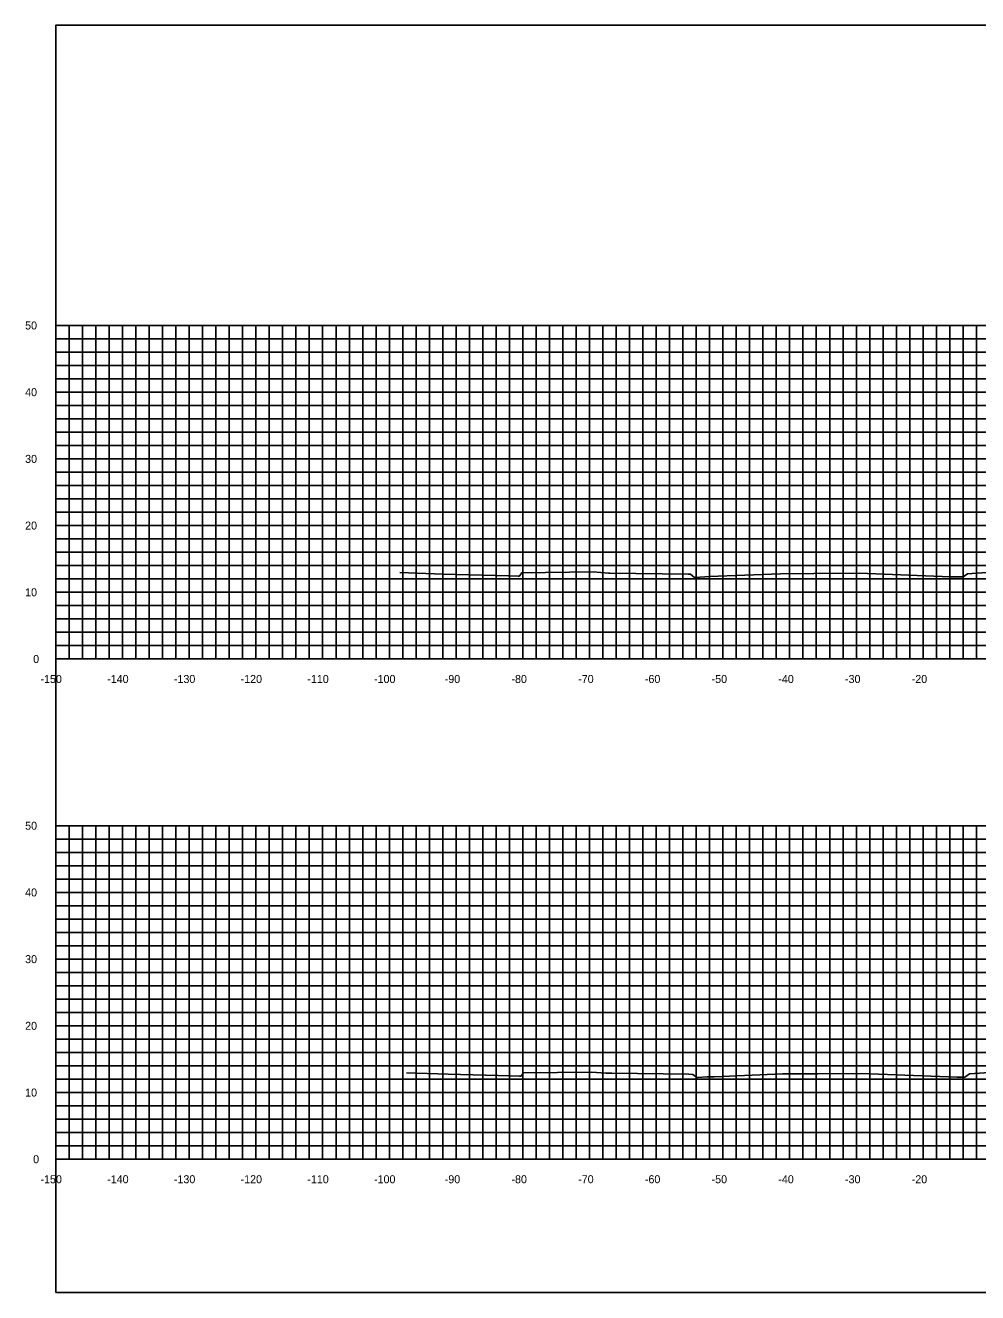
# Model space of a CAD drawing. Extents: x 1797714 to 1804825, y 249015 to 250269.
# Drawn here: x 1803809.6 to 1803952.3, y 249628.2 to 249818.2 of the extents above; entities that cross this region are included whole.
import ezdxf

# ---------------------------------------------------------------- set-up
doc = ezdxf.new("R2010")
doc.units = 0
for name, color, linetype in [('10', 7, 'Continuous'), ('31', 7, 'Continuous'), ('60', 7, 'Continuous'), ('Level 62', 7, 'Continuous'), ('M-ROADS', 7, 'Continuous')]:
    doc.layers.add(name, color=color, linetype=linetype)

msp = doc.modelspace()

# ---------------------------------------------------------------- linework, layer by layer
msp.add_lwpolyline([(1803814.16, 249628.17), (1804114.16, 249628.17), (1804114.16, 249818.17), (1803814.16, 249818.17)], close=True)
at = {"layer": '60'}
for p, q in [((1803814.1, 249773.17), (1803814.16, 249773.17)), ((1803814.16, 249723.17), (1803814.16, 249773.17)), ((1803814.1, 249763.17), (1803814.16, 249763.17)), ((1803814.1, 249753.17), (1803814.16, 249753.17)), ((1803814.1, 249743.17), (1803814.16, 249743.17)), ((1803814.1, 249733.17), (1803814.16, 249733.17)), ((1803814.1, 249723.17), (1803814.16, 249723.17)), ((1803814.16, 249723.17), (1804114.16, 249723.17)), ((1803814.16, 249723.11), (1803814.16, 249723.17)), ((1803824.16, 249723.11), (1803824.16, 249723.17)), ((1803834.16, 249723.11), (1803834.16, 249723.17)), ((1803844.16, 249723.11), (1803844.16, 249723.17)), ((1803854.16, 249723.11), (1803854.16, 249723.17)), ((1803864.16, 249723.11), (1803864.16, 249723.17)), ((1803874.16, 249723.11), (1803874.16, 249723.17)), ((1803884.16, 249723.11), (1803884.16, 249723.17)), ((1803894.16, 249723.11), (1803894.16, 249723.17)), ((1803904.16, 249723.11), (1803904.16, 249723.17)), ((1803914.16, 249723.11), (1803914.16, 249723.17)), ((1803924.16, 249723.11), (1803924.16, 249723.17)), ((1803934.16, 249723.11), (1803934.16, 249723.17)), ((1803944.16, 249723.11), (1803944.16, 249723.17)), ((1803814.1, 249698.17), (1803814.16, 249698.17)), ((1803814.16, 249648.17), (1803814.16, 249698.17)), ((1803814.1, 249688.17), (1803814.16, 249688.17)), ((1803814.1, 249678.17), (1803814.16, 249678.17)), ((1803814.1, 249668.17), (1803814.16, 249668.17)), ((1803814.1, 249658.17), (1803814.16, 249658.17)), ((1803814.1, 249648.17), (1803814.16, 249648.17)), ((1803814.16, 249648.17), (1804114.16, 249648.17)), ((1803814.16, 249648.11), (1803814.16, 249648.17)), ((1803824.16, 249648.11), (1803824.16, 249648.17)), ((1803834.16, 249648.11), (1803834.16, 249648.17)), ((1803844.16, 249648.11), (1803844.16, 249648.17)), ((1803854.16, 249648.11), (1803854.16, 249648.17)), ((1803864.16, 249648.11), (1803864.16, 249648.17)), ((1803874.16, 249648.11), (1803874.16, 249648.17)), ((1803884.16, 249648.11), (1803884.16, 249648.17)), ((1803894.16, 249648.11), (1803894.16, 249648.17)), ((1803904.16, 249648.11), (1803904.16, 249648.17)), ((1803914.16, 249648.11), (1803914.16, 249648.17)), ((1803924.16, 249648.11), (1803924.16, 249648.17)), ((1803934.16, 249648.11), (1803934.16, 249648.17)), ((1803944.16, 249648.11), (1803944.16, 249648.17))]:
    msp.add_line(p, q, dxfattribs=at)
at = {"layer": 'Level 62'}
for p, q in [((1803814.16, 249773.17), (1804114.16, 249773.17)), ((1803814.16, 249723.17), (1803814.16, 249773.17)), ((1803816.16, 249723.17), (1803816.16, 249773.17)), ((1803818.16, 249723.17), (1803818.16, 249773.17)), ((1803820.16, 249723.17), (1803820.16, 249773.17)), ((1803822.16, 249723.17), (1803822.16, 249773.17)), ((1803824.16, 249723.17), (1803824.16, 249773.17)), ((1803826.16, 249723.17), (1803826.16, 249773.17)), ((1803828.16, 249723.17), (1803828.16, 249773.17)), ((1803830.16, 249723.17), (1803830.16, 249773.17)), ((1803832.16, 249723.17), (1803832.16, 249773.17)), ((1803834.16, 249723.17), (1803834.16, 249773.17)), ((1803836.16, 249723.17), (1803836.16, 249773.17)), ((1803838.16, 249723.17), (1803838.16, 249773.17)), ((1803840.16, 249723.17), (1803840.16, 249773.17)), ((1803842.16, 249723.17), (1803842.16, 249773.17)), ((1803844.16, 249723.17), (1803844.16, 249773.17)), ((1803846.16, 249723.17), (1803846.16, 249773.17)), ((1803848.16, 249723.17), (1803848.16, 249773.17)), ((1803850.16, 249723.17), (1803850.16, 249773.17)), ((1803852.16, 249723.17), (1803852.16, 249773.17)), ((1803854.16, 249723.17), (1803854.16, 249773.17)), ((1803856.16, 249723.17), (1803856.16, 249773.17)), ((1803858.16, 249723.17), (1803858.16, 249773.17)), ((1803860.16, 249723.17), (1803860.16, 249773.17)), ((1803862.16, 249723.17), (1803862.16, 249773.17)), ((1803864.16, 249723.17), (1803864.16, 249773.17)), ((1803866.16, 249723.17), (1803866.16, 249773.17)), ((1803868.16, 249723.17), (1803868.16, 249773.17)), ((1803870.16, 249723.17), (1803870.16, 249773.17)), ((1803872.16, 249723.17), (1803872.16, 249773.17)), ((1803874.16, 249723.17), (1803874.16, 249773.17)), ((1803876.16, 249723.17), (1803876.16, 249773.17)), ((1803878.16, 249723.17), (1803878.16, 249773.17)), ((1803880.16, 249723.17), (1803880.16, 249773.17)), ((1803882.16, 249723.17), (1803882.16, 249773.17)), ((1803884.16, 249723.17), (1803884.16, 249773.17)), ((1803886.16, 249723.17), (1803886.16, 249773.17)), ((1803888.16, 249723.17), (1803888.16, 249773.17)), ((1803890.16, 249723.17), (1803890.16, 249773.17)), ((1803892.16, 249723.17), (1803892.16, 249773.17)), ((1803894.16, 249723.17), (1803894.16, 249773.17)), ((1803896.16, 249723.17), (1803896.16, 249773.17)), ((1803898.16, 249723.17), (1803898.16, 249773.17)), ((1803900.16, 249723.17), (1803900.16, 249773.17)), ((1803902.16, 249723.17), (1803902.16, 249773.17)), ((1803904.16, 249723.17), (1803904.16, 249773.17)), ((1803906.16, 249723.17), (1803906.16, 249773.17)), ((1803908.16, 249723.17), (1803908.16, 249773.17)), ((1803910.16, 249723.17), (1803910.16, 249773.17)), ((1803912.16, 249723.17), (1803912.16, 249773.17)), ((1803914.16, 249723.17), (1803914.16, 249773.17)), ((1803916.16, 249723.17), (1803916.16, 249773.17)), ((1803918.16, 249723.17), (1803918.16, 249773.17)), ((1803920.16, 249723.17), (1803920.16, 249773.17)), ((1803922.16, 249723.17), (1803922.16, 249773.17)), ((1803924.16, 249723.17), (1803924.16, 249773.17)), ((1803926.16, 249723.17), (1803926.16, 249773.17)), ((1803928.16, 249723.17), (1803928.16, 249773.17)), ((1803930.16, 249723.17), (1803930.16, 249773.17)), ((1803932.16, 249723.17), (1803932.16, 249773.17)), ((1803934.16, 249723.17), (1803934.16, 249773.17)), ((1803936.16, 249723.17), (1803936.16, 249773.17)), ((1803938.16, 249723.17), (1803938.16, 249773.17)), ((1803940.16, 249723.17), (1803940.16, 249773.17)), ((1803942.16, 249723.17), (1803942.16, 249773.17)), ((1803944.16, 249723.17), (1803944.16, 249773.17)), ((1803946.16, 249723.17), (1803946.16, 249773.17)), ((1803948.16, 249723.17), (1803948.16, 249773.17)), ((1803950.16, 249723.17), (1803950.16, 249773.17)), ((1803952.16, 249723.17), (1803952.16, 249773.17)), ((1803814.16, 249771.17), (1804114.16, 249771.17)), ((1803814.16, 249769.17), (1804114.16, 249769.17)), ((1803814.16, 249767.17), (1804114.16, 249767.17)), ((1803814.16, 249765.17), (1804114.16, 249765.17)), ((1803814.16, 249763.17), (1804114.16, 249763.17)), ((1803814.16, 249761.17), (1804114.16, 249761.17)), ((1803814.16, 249759.17), (1804114.16, 249759.17)), ((1803814.16, 249757.17), (1804114.16, 249757.17)), ((1803814.16, 249755.17), (1804114.16, 249755.17)), ((1803814.16, 249753.17), (1804114.16, 249753.17)), ((1803814.16, 249751.17), (1804114.16, 249751.17)), ((1803814.16, 249749.17), (1804114.16, 249749.17)), ((1803814.16, 249747.17), (1804114.16, 249747.17)), ((1803814.16, 249745.17), (1804114.16, 249745.17)), ((1803814.16, 249743.17), (1804114.16, 249743.17)), ((1803814.16, 249741.17), (1804114.16, 249741.17)), ((1803814.16, 249739.17), (1804114.16, 249739.17)), ((1803814.16, 249737.17), (1804114.16, 249737.17)), ((1803814.16, 249735.17), (1804114.16, 249735.17)), ((1803814.16, 249733.17), (1804114.16, 249733.17)), ((1803814.16, 249731.17), (1804114.16, 249731.17)), ((1803814.16, 249729.17), (1804114.16, 249729.17)), ((1803814.16, 249727.17), (1804114.16, 249727.17)), ((1803814.16, 249725.17), (1804114.16, 249725.17)), ((1803814.16, 249723.17), (1804114.16, 249723.17)), ((1803814.16, 249698.17), (1804114.16, 249698.17)), ((1803814.16, 249648.17), (1803814.16, 249698.17)), ((1803816.16, 249648.17), (1803816.16, 249698.17)), ((1803818.16, 249648.17), (1803818.16, 249698.17)), ((1803820.16, 249648.17), (1803820.16, 249698.17)), ((1803822.16, 249648.17), (1803822.16, 249698.17)), ((1803824.16, 249648.17), (1803824.16, 249698.17)), ((1803826.16, 249648.17), (1803826.16, 249698.17)), ((1803828.16, 249648.17), (1803828.16, 249698.17)), ((1803830.16, 249648.17), (1803830.16, 249698.17)), ((1803832.16, 249648.17), (1803832.16, 249698.17)), ((1803834.16, 249648.17), (1803834.16, 249698.17)), ((1803836.16, 249648.17), (1803836.16, 249698.17)), ((1803838.16, 249648.17), (1803838.16, 249698.17)), ((1803840.16, 249648.17), (1803840.16, 249698.17)), ((1803842.16, 249648.17), (1803842.16, 249698.17)), ((1803844.16, 249648.17), (1803844.16, 249698.17)), ((1803846.16, 249648.17), (1803846.16, 249698.17)), ((1803848.16, 249648.17), (1803848.16, 249698.17)), ((1803850.16, 249648.17), (1803850.16, 249698.17)), ((1803852.16, 249648.17), (1803852.16, 249698.17)), ((1803854.16, 249648.17), (1803854.16, 249698.17)), ((1803856.16, 249648.17), (1803856.16, 249698.17)), ((1803858.16, 249648.17), (1803858.16, 249698.17)), ((1803860.16, 249648.17), (1803860.16, 249698.17)), ((1803862.16, 249648.17), (1803862.16, 249698.17)), ((1803864.16, 249648.17), (1803864.16, 249698.17)), ((1803866.16, 249648.17), (1803866.16, 249698.17)), ((1803868.16, 249648.17), (1803868.16, 249698.17)), ((1803870.16, 249648.17), (1803870.16, 249698.17)), ((1803872.16, 249648.17), (1803872.16, 249698.17)), ((1803874.16, 249648.17), (1803874.16, 249698.17)), ((1803876.16, 249648.17), (1803876.16, 249698.17)), ((1803878.16, 249648.17), (1803878.16, 249698.17)), ((1803880.16, 249648.17), (1803880.16, 249698.17)), ((1803882.16, 249648.17), (1803882.16, 249698.17)), ((1803884.16, 249648.17), (1803884.16, 249698.17)), ((1803886.16, 249648.17), (1803886.16, 249698.17)), ((1803888.16, 249648.17), (1803888.16, 249698.17)), ((1803890.16, 249648.17), (1803890.16, 249698.17)), ((1803892.16, 249648.17), (1803892.16, 249698.17)), ((1803894.16, 249648.17), (1803894.16, 249698.17)), ((1803896.16, 249648.17), (1803896.16, 249698.17)), ((1803898.16, 249648.17), (1803898.16, 249698.17)), ((1803900.16, 249648.17), (1803900.16, 249698.17)), ((1803902.16, 249648.17), (1803902.16, 249698.17)), ((1803904.16, 249648.17), (1803904.16, 249698.17)), ((1803906.16, 249648.17), (1803906.16, 249698.17)), ((1803908.16, 249648.17), (1803908.16, 249698.17)), ((1803910.16, 249648.17), (1803910.16, 249698.17)), ((1803912.16, 249648.17), (1803912.16, 249698.17)), ((1803914.16, 249648.17), (1803914.16, 249698.17)), ((1803916.16, 249648.17), (1803916.16, 249698.17)), ((1803918.16, 249648.17), (1803918.16, 249698.17)), ((1803920.16, 249648.17), (1803920.16, 249698.17)), ((1803922.16, 249648.17), (1803922.16, 249698.17)), ((1803924.16, 249648.17), (1803924.16, 249698.17)), ((1803926.16, 249648.17), (1803926.16, 249698.17)), ((1803928.16, 249648.17), (1803928.16, 249698.17)), ((1803930.16, 249648.17), (1803930.16, 249698.17)), ((1803932.16, 249648.17), (1803932.16, 249698.17)), ((1803934.16, 249648.17), (1803934.16, 249698.17)), ((1803936.16, 249648.17), (1803936.16, 249698.17)), ((1803938.16, 249648.17), (1803938.16, 249698.17)), ((1803940.16, 249648.17), (1803940.16, 249698.17)), ((1803942.16, 249648.17), (1803942.16, 249698.17)), ((1803944.16, 249648.17), (1803944.16, 249698.17)), ((1803946.16, 249648.17), (1803946.16, 249698.17)), ((1803948.16, 249648.17), (1803948.16, 249698.17)), ((1803950.16, 249648.17), (1803950.16, 249698.17)), ((1803952.16, 249648.17), (1803952.16, 249698.17)), ((1803814.16, 249696.17), (1804114.16, 249696.17)), ((1803814.16, 249694.17), (1804114.16, 249694.17)), ((1803814.16, 249692.17), (1804114.16, 249692.17)), ((1803814.16, 249690.17), (1804114.16, 249690.17)), ((1803814.16, 249688.17), (1804114.16, 249688.17)), ((1803814.16, 249686.17), (1804114.16, 249686.17)), ((1803814.16, 249684.17), (1804114.16, 249684.17)), ((1803814.16, 249682.17), (1804114.16, 249682.17)), ((1803814.16, 249680.17), (1804114.16, 249680.17)), ((1803814.16, 249678.17), (1804114.16, 249678.17)), ((1803814.16, 249676.17), (1804114.16, 249676.17)), ((1803814.16, 249674.17), (1804114.16, 249674.17)), ((1803814.16, 249672.17), (1804114.16, 249672.17)), ((1803814.16, 249670.17), (1804114.16, 249670.17)), ((1803814.16, 249668.17), (1804114.16, 249668.17)), ((1803814.16, 249666.17), (1804114.16, 249666.17)), ((1803814.16, 249664.17), (1804114.16, 249664.17)), ((1803814.16, 249662.17), (1804114.16, 249662.17)), ((1803814.16, 249660.17), (1804114.16, 249660.17)), ((1803814.16, 249658.17), (1804114.16, 249658.17)), ((1803814.16, 249656.17), (1804114.16, 249656.17)), ((1803814.16, 249654.17), (1804114.16, 249654.17)), ((1803814.16, 249652.17), (1804114.16, 249652.17)), ((1803814.16, 249650.17), (1804114.16, 249650.17)), ((1803814.16, 249648.17), (1804114.16, 249648.17))]:
    msp.add_line(p, q, dxfattribs=at)
at = {"layer": 'M-ROADS'}
for points in [[(1803865.71, 249736.16), (1803872.23, 249735.91), (1803882.04, 249735.66), (1803883.47, 249735.61), (1803883.65, 249735.61), (1803883.7, 249735.67), (1803884, 249736.1), (1803894.7, 249736.24), (1803896.99, 249736.03), (1803897.19, 249736.03), (1803908.96, 249735.89), (1803909.32, 249735.88), (1803909.9, 249735.41), (1803909.91, 249735.39), (1803909.96, 249735.4), (1803911.46, 249735.49), (1803912.11, 249735.52), (1803922.8, 249735.94), (1803927.8, 249735.98), (1803934.59, 249736.03), (1803948.26, 249735.51), (1803948.98, 249735.49), (1803949.13, 249735.49), (1803949.23, 249735.49), (1803949.33, 249735.49), (1803949.4, 249735.49), (1803949.46, 249735.49), (1803950.17, 249735.48), (1803950.3, 249735.61), (1803950.84, 249735.96), (1803954.39, 249736.19)], [(1803866.73, 249661.14), (1803872.95, 249660.91), (1803882.32, 249660.67), (1803883.68, 249660.62), (1803883.91, 249660.62), (1803883.98, 249660.7), (1803884.27, 249661.11), (1803894.48, 249661.24), (1803896.67, 249661.05), (1803897.53, 249661.05), (1803909.04, 249660.9), (1803909.66, 249660.88), (1803910.23, 249660.43), (1803910.25, 249660.4), (1803910.34, 249660.41), (1803911.8, 249660.5), (1803912.86, 249660.54), (1803923.11, 249660.95), (1803928.39, 249660.99), (1803934.9, 249661.04), (1803949.27, 249660.49), (1803949.42, 249660.49), (1803949.53, 249660.49), (1803949.64, 249660.49), (1803949.72, 249660.49), (1803949.78, 249660.49), (1803949.84, 249660.49), (1803950.44, 249660.48), (1803950.55, 249660.59), (1803951.12, 249660.96), (1803954.14, 249661.16)]]:
    msp.add_lwpolyline(points, dxfattribs=at)

# ---------------------------------------------------------------- texts
at = {"layer": '10'}
for s, p in [('-150', (1803811.86, 249719.57)), ('-140', (1803821.86, 249719.57)), ('-130', (1803831.86, 249719.57)), ('-120', (1803841.86, 249719.57)), ('-110', (1803851.86, 249719.57)), ('-100', (1803861.86, 249719.57)), ('-90', (1803872.46, 249719.57)), ('-80', (1803882.46, 249719.57)), ('-70', (1803892.46, 249719.57)), ('-60', (1803902.46, 249719.57)), ('-50', (1803912.46, 249719.57)), ('-40', (1803922.46, 249719.57)), ('-30', (1803932.46, 249719.57)), ('-20', (1803942.46, 249719.57)), ('-150', (1803811.86, 249644.57)), ('-140', (1803821.86, 249644.57)), ('-130', (1803831.86, 249644.57)), ('-120', (1803841.86, 249644.57)), ('-110', (1803851.86, 249644.57)), ('-100', (1803861.86, 249644.57)), ('-90', (1803872.46, 249644.57)), ('-80', (1803882.46, 249644.57)), ('-70', (1803892.46, 249644.57)), ('-60', (1803902.46, 249644.57)), ('-50', (1803912.46, 249644.57)), ('-40', (1803922.46, 249644.57)), ('-30', (1803932.46, 249644.57)), ('-20', (1803942.46, 249644.57))]:
    msp.add_text(s, height=1.2, dxfattribs=at).set_placement(p)
at = {"layer": '31'}
for s, p in [('50', (1803809.56, 249772.57)), ('40', (1803809.56, 249762.57)), ('30', (1803809.56, 249752.57)), ('20', (1803809.56, 249742.57)), ('10', (1803809.56, 249732.57)), ('0', (1803810.76, 249722.57)), ('50', (1803809.56, 249697.57)), ('40', (1803809.56, 249687.57)), ('30', (1803809.56, 249677.57)), ('20', (1803809.56, 249667.57)), ('10', (1803809.56, 249657.57)), ('0', (1803810.76, 249647.57))]:
    msp.add_text(s, height=1.2, dxfattribs=at).set_placement(p)
at = {"layer": '60'}
for p in [(1803814.16, 249723.17), (1803814.16, 249648.17)]:
    msp.add_text('-', height=0.0001, dxfattribs=at).set_placement(p)

doc.saveas('drawing.dxf')
